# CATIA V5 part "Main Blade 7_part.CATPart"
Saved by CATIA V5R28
Part number: Main Blade 7_part
Definition: design
Nomenclature: Main Blade 7_part
Source: Unknown
Bounding box of the stored display mesh (mm): x -6.778 to -1.267, y -4.236 to 7.597, z 1.529 to 7.748
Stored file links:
  D:\paraturbo-cad\STEP\Turbocompressor_for_Christophe\Main Blade 7_part.CATPart
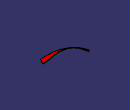
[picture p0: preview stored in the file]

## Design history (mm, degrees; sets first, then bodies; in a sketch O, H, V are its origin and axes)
Body1 "MANIFOLD_SOLID_BREP #50270" (main body)
  Solid1: solid without history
